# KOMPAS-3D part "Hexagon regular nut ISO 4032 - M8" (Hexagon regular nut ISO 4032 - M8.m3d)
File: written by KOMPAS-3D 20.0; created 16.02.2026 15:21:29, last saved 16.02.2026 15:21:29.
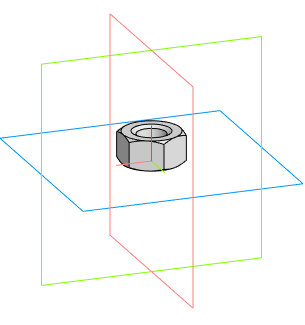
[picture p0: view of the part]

Document properties: Автор: admin; Полное имя файла: P:\INSTART\Технический отдел\ОР\Прочие задачи\КД на номенклатурный ряд\КД на типоразмеры дросселей\Сетевые дроссели ISF\ISF-4\Тип 1\ISF-132_256-4\0723\Новая папка\Hexagon regular nut ISO 4032 - M8.m3d

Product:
- Part/product: Hexagon regular nut ISO 4032 - M8

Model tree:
1. Операция без истории:1  (labels: Hexagon regular nut ISO 4032 - M8)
